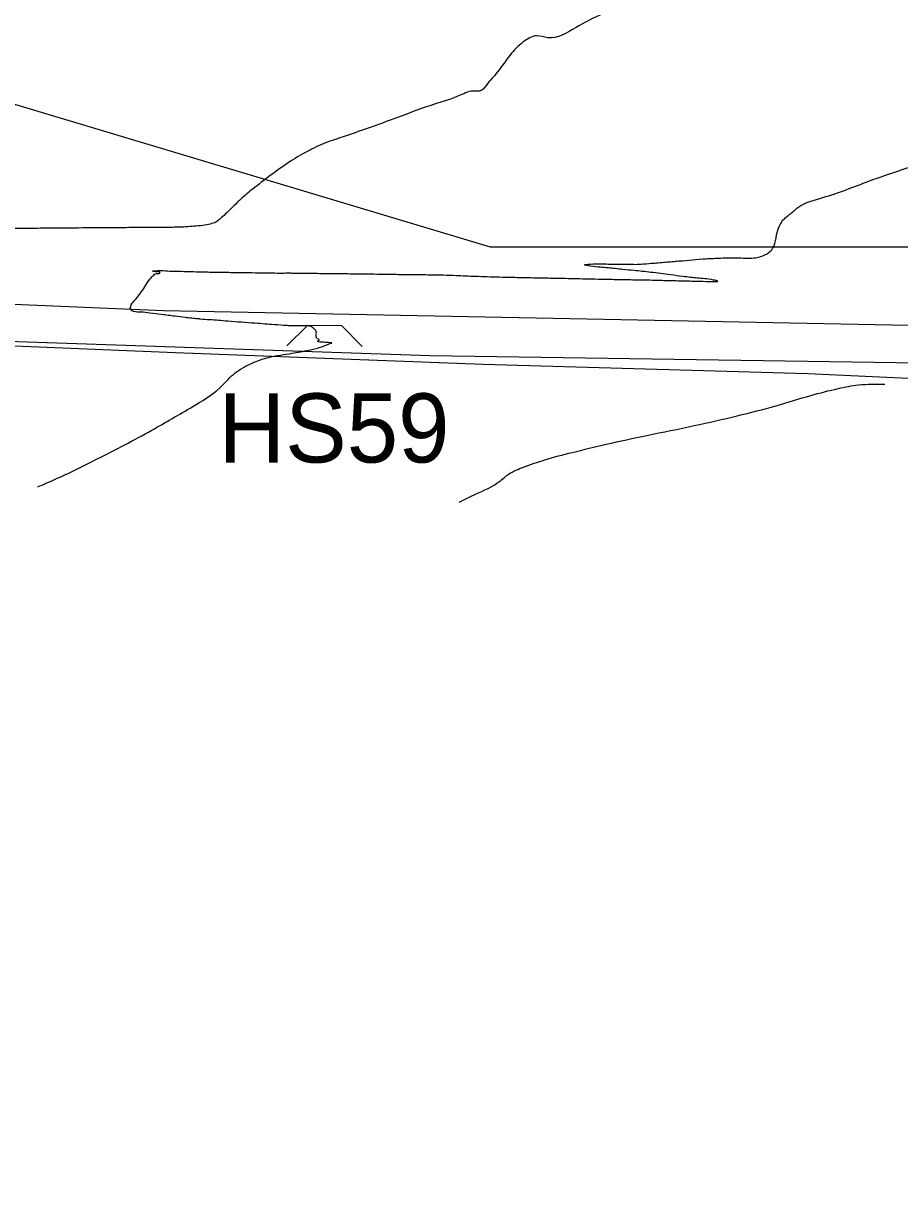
# Model space of a CAD drawing. Extents: x -478232 to -472707, y -1118753 to -1113967.
# Drawn here: x -477352.7 to -477225.9, y -1117543.2 to -1117372.8 of the extents above; entities that cross this region are included whole.
import ezdxf

# ---------------------------------------------------------------- set-up
doc = ezdxf.new("R2010")
doc.units = 0
for name, color, linetype in [('DESQ_pomoc', 7, 'Continuous'), ('hospodářské sjezdy', 7, 'Continuous'), ('ObPÚ', 7, 'Continuous'), ('silnice', 7, 'Continuous'), ('Vrstevnice_hlavni', 7, 'Continuous'), ('Vrstevnice_vedlejsi', 7, 'Continuous')]:
    doc.layers.add(name, color=color, linetype=linetype)

msp = doc.modelspace()

# ---------------------------------------------------------------- linework, layer by layer
at = {"layer": 'DESQ_pomoc'}
for points in [[(-477004.483, -1117160.333), (-477044.314, -1117201.613), (-476989.999, -1117272.585), (-476948.719, -1117345.73), (-476963.565, -1117360.938), (-477094.646, -1117397.148), (-477179.378, -1117405.115), (-477285.113, -1117405.115), (-477363.689, -1117381.578), (-477420.306, -1117340.062)], [(-477020.868, -1117742.21), (-477020.868, -1117712.88), (-477044.921, -1117619.616), (-477020.387, -1117525.382), (-477007.841, -1117474.78), (-476980.24, -1117427.384), (-476963.584, -1117391.711), (-476964.987, -1117380.26), (-476992.688, -1117391.394), (-477072.131, -1117410.121), (-477126.017, -1117419.251), (-477181.42, -1117422.538), (-477293.867, -1117420.815), (-477420.422, -1117416.561)]]:
    msp.add_lwpolyline(points, dxfattribs=at)
at = {"layer": 'hospodářské sjezdy'}
for p, q in [((-477314.616, -1117419.39), (-477311.569, -1117416.405)), ((-477311.569, -1117416.405), (-477306.684, -1117416.452)), ((-477306.684, -1117416.452), (-477303.695, -1117419.496))]:
    msp.add_line(p, q, dxfattribs=at)
at = {"layer": 'ObPÚ'}
msp.add_lwpolyline([(-476315.84, -1117537.76), (-476383.34, -1117541.03), (-476418.4, -1117542.71), (-476545.68, -1117541.31), (-476626.45, -1117531.73), (-476742.52, -1117514.65), (-476868.42, -1117495.62), (-476991.41, -1117464.75), (-477034.12, -1117456), (-477098.26, -1117446.89), (-477099.13, -1117418.94), (-477133.34, -1117422.81), (-477164.02, -1117425.11), (-477192.43, -1117425.62), (-477239.17, -1117423.45), (-477286.2, -1117422.09), (-477330.75, -1117420.42), (-477373.93, -1117418.61), (-477420.9, -1117417.49), (-477422.1, -1117417.56), (-477424.2, -1117417.6), (-477428.82, -1117417.33), (-477494.83, -1117414.18)], dxfattribs=at)
at = {"layer": 'silnice'}
msp.add_lwpolyline([(-478068.596, -1117511.329), (-477917.95, -1117462.993), (-477779.219, -1117418.245), (-477732.944, -1117407.585), (-477720.808, -1117405.048), (-477704.588, -1117403.835), (-477689.402, -1117401.926), (-477652.852, -1117401.691), (-477590.784, -1117403.37), (-477332.447, -1117414.279), (-477204.956, -1117416.797), (-477142.049, -1117416.797), (-477096.756, -1117410.083), (-477036.34, -1117397.174), (-476978.492, -1117379.033), (-476883.712, -1117344.626), (-476756.221, -1117298.47), (-476633.763, -1117254.832), (-476588.47, -1117242.245), (-476550.726, -1117234.692), (-476503.755, -1117230.496), (-476424.073, -1117228.817), (-476282.324, -1117220.425)], dxfattribs=at)
at = {"layer": 'Vrstevnice_hlavni'}
msp.add_spline([(-477289.678, -1117442), (-477287.302, -1117440.862), (-477283.774, -1117438.986), (-477282.509, -1117437.973), (-477280.339, -1117436.941), (-477277.265, -1117435.89), (-477273.286, -1117434.82), (-477268.352, -1117433.639), (-477262.464, -1117432.347), (-477255.622, -1117430.943), (-477249.39, -1117429.513), (-477243.767, -1117428.058), (-477238.754, -1117426.577), (-477234.779, -1117425.573), (-477231.842, -1117425.045), (-477228.043, -1117424.944)], degree=3, dxfattribs=at)
at = {"layer": 'Vrstevnice_vedlejsi'}
for points in [[(-477242.816, -1117401.206), (-477242.33, -1117400.788), (-477241.801, -1117400.341), (-477241.229, -1117399.866), (-477240.615, -1117399.363), (-477236.987, -1117397.929), (-477230.346, -1117395.561), (-477220.692, -1117392.262), (-477213.029, -1117389.419), (-477207.358, -1117387.033), (-477203.679, -1117385.104), (-477198.765, -1117383.705), (-477192.616, -1117382.835), (-477185.231, -1117382.494), (-477180.359, -1117379.804), (-477178.001, -1117374.763), (-477178.155, -1117367.373), (-477179.951, -1117358.721), (-477183.387, -1117348.807), (-477188.465, -1117337.631), (-477192.245, -1117329.464), (-477194.727, -1117324.304), (-477195.91, -1117322.151), (-477197.022, -1117320.01), (-477198.062, -1117317.881), (-477199.031, -1117315.762), (-477201.828, -1117310.612), (-477206.453, -1117302.429), (-477212.906, -1117291.215), (-477218.991, -1117279.805), (-477224.706, -1117268.2), (-477230.053, -1117256.4), (-477233.791, -1117248.023), (-477235.922, -1117243.067), (-477236.445, -1117241.534), (-477237.131, -1117240.196), (-477237.979, -1117239.054), (-477238.989, -1117238.108), (-477240.099, -1117237.792), (-477241.308, -1117238.108), (-477242.616, -1117239.054), (-477247.496, -1117242.927), (-477255.949, -1117249.728), (-477267.975, -1117259.456), (-477276.908, -1117266.227), (-477282.75, -1117270.039), (-477285.501, -1117270.894), (-477290.862, -1117272.253), (-477298.834, -1117274.115), (-477309.417, -1117276.481), (-477320.28, -1117277.55), (-477331.422, -1117277.32), (-477342.843, -1117275.793), (-477351.095, -1117274.483), (-477356.177, -1117273.39), (-477358.088, -1117272.515), (-477363.807, -1117268.569), (-477373.333, -1117261.552), (-477386.667, -1117251.464), (-477395.708, -1117244.586), (-477400.459, -1117240.917), (-477400.917, -1117240.459), (-477405.515, -1117237.519), (-477414.252, -1117232.098), (-477427.127, -1117224.195), (-477436.796, -1117218.202), (-477443.259, -1117214.119), (-477446.516, -1117211.946), (-477449.727, -1117209.411), (-477452.893, -1117206.515), (-477456.014, -1117203.258), (-477459.048, -1117199.241), (-477461.994, -1117194.464), (-477464.853, -1117188.928), (-477466.734, -1117184.683), (-477467.638, -1117181.729), (-477467.564, -1117180.066), (-477467.628, -1117178.904), (-477467.829, -1117178.243), (-477468.169, -1117178.084), (-477468.447, -1117177.976), (-477468.662, -1117177.92), (-477468.815, -1117177.914), (-477468.774, -1117177.844), (-477468.538, -1117177.708), (-477468.108, -1117177.506), (-477467.675, -1117177.3), (-477467.24, -1117177.089), (-477466.803, -1117176.874), (-477466.105, -1117176.551), (-477465.147, -1117176.119), (-477463.929, -1117175.579), (-477461.972, -1117174.773), (-477459.277, -1117173.703), (-477455.843, -1117172.368), (-477453.286, -1117171.289), (-477451.604, -1117170.465)], [(-477252.72, -1117332.72), (-477249.442, -1117350.907), (-477251.399, -1117358.647), (-477256.954, -1117365.034), (-477266.106, -1117370.068), (-477272.734, -1117373.328), (-477276.839, -1117374.815), (-477278.419, -1117374.529), (-477280.163, -1117375.266), (-477282.069, -1117377.024), (-477284.137, -1117379.804), (-477285.708, -1117381.646), (-477286.782, -1117382.55), (-477287.358, -1117382.516), (-477289.514, -1117383.138), (-477293.25, -1117384.416), (-477298.565, -1117386.349), (-477302.966, -1117387.928), (-477306.451, -1117389.154), (-477309.021, -1117390.026), (-477311.669, -1117391.276), (-477314.394, -1117392.903), (-477317.197, -1117394.908), (-477319.486, -1117396.657), (-477321.26, -1117398.15), (-477322.52, -1117399.387), (-477323.516, -1117400.341), (-477324.249, -1117401.012), (-477324.718, -1117401.399), (-477325.454, -1117401.703), (-477326.457, -1117401.923), (-477327.727, -1117402.06), (-477328.933, -1117402.16), (-477330.077, -1117402.221), (-477331.158, -1117402.245), (-477332.75, -1117402.264), (-477334.854, -1117402.279), (-477337.471, -1117402.29), (-477340.599, -1117402.31), (-477344.24, -1117402.337), (-477348.392, -1117402.371), (-477351.464, -1117402.395), (-477353.456, -1117402.406), (-477354.368, -1117402.406), (-477355.068, -1117402.403), (-477355.558, -1117402.399), (-477355.837, -1117402.392), (-477356.81, -1117402.42), (-477358.476, -1117402.483), (-477360.836, -1117402.58), (-477361.948, -1117402.705), (-477361.81, -1117402.861), (-477360.423, -1117403.045), (-477359.31, -1117403.205), (-477358.471, -1117403.34), (-477357.906, -1117403.451), (-477357.287, -1117403.611), (-477356.616, -1117403.818), (-477355.892, -1117404.072), (-477355.822, -1117404.241), (-477356.404, -1117404.324), (-477357.64, -1117404.32), (-477359.149, -1117404.327), (-477360.932, -1117404.343), (-477362.988, -1117404.369), (-477364.621, -1117404.377), (-477365.832, -1117404.368), (-477366.619, -1117404.34), (-477368.472, -1117404.314), (-477371.39, -1117404.29), (-477375.373, -1117404.266), (-477378.256, -1117404.244), (-477380.04, -1117404.225), (-477380.724, -1117404.208), (-477382.599, -1117404.115), (-477385.666, -1117403.945), (-477389.925, -1117403.698), (-477392.944, -1117403.533), (-477394.725, -1117403.45), (-477395.267, -1117403.448), (-477395.831, -1117403.442), (-477396.419, -1117403.433), (-477397.029, -1117403.42), (-477399.108, -1117403.384), (-477402.657, -1117403.323), (-477407.675, -1117403.239), (-477411.11, -1117403.18), (-477412.96, -1117403.147), (-477413.228, -1117403.138), (-477413.484, -1117403.113), (-477413.73, -1117403.071), (-477413.965, -1117403.013), (-477414.17, -1117402.951), (-477414.344, -1117402.886), (-477414.489, -1117402.817), (-477414.611, -1117402.734), (-477414.713, -1117402.635)], [(-477327.901, -1117415.45), (-477328.37, -1117415.407), (-477329.337, -1117415.294), (-477330.802, -1117415.109), (-477332.763, -1117414.853), (-477334.415, -1117414.652), (-477335.757, -1117414.508), (-477336.789, -1117414.419), (-477337.25, -1117414.076), (-477337.139, -1117413.48), (-477336.456, -1117412.63), (-477335.796, -1117411.752), (-477335.159, -1117410.844), (-477334.546, -1117409.906), (-477333.982, -1117409.264), (-477333.469, -1117408.918), (-477333.006, -1117408.867), (-477332.952, -1117408.792), (-477333.306, -1117408.693), (-477334.069, -1117408.572), (-477333.693, -1117408.518), (-477332.176, -1117408.533), (-477329.52, -1117408.616), (-477327.678, -1117408.673), (-477326.65, -1117408.701), (-477326.435, -1117408.702), (-477325.121, -1117408.721), (-477322.709, -1117408.756), (-477319.198, -1117408.809), (-477316.698, -1117408.842), (-477315.21, -1117408.856), (-477314.734, -1117408.85), (-477314.188, -1117408.85), (-477313.571, -1117408.855), (-477312.885, -1117408.866), (-477311.356, -1117408.884), (-477308.985, -1117408.911), (-477305.772, -1117408.946), (-477303.301, -1117408.975), (-477301.572, -1117408.998), (-477300.585, -1117409.016), (-477299.025, -1117409.038), (-477296.891, -1117409.065), (-477294.184, -1117409.097), (-477291.924, -1117409.139), (-477290.111, -1117409.192), (-477288.744, -1117409.255), (-477287.246, -1117409.315), (-477285.617, -1117409.37), (-477283.855, -1117409.421), (-477281.83, -1117409.471), (-477279.54, -1117409.519), (-477276.987, -1117409.566), (-477274.786, -1117409.61), (-477272.936, -1117409.65), (-477271.438, -1117409.687), (-477269.537, -1117409.727), (-477267.234, -1117409.771), (-477264.529, -1117409.817), (-477262.433, -1117409.857), (-477260.946, -1117409.889), (-477260.07, -1117409.915), (-477258.516, -1117409.953), (-477256.285, -1117410.005), (-477253.377, -1117410.07), (-477252.223, -1117410.023), (-477252.824, -1117409.865), (-477255.18, -1117409.597), (-477257.247, -1117409.351), (-477259.025, -1117409.129), (-477260.513, -1117408.931), (-477261.893, -1117408.76), (-477263.165, -1117408.617), (-477264.329, -1117408.502), (-477265.966, -1117408.334), (-477268.076, -1117408.115), (-477270.659, -1117407.844), (-477271.519, -1117407.66), (-477270.654, -1117407.563), (-477268.065, -1117407.553), (-477266.158, -1117407.555), (-477264.933, -1117407.569), (-477264.39, -1117407.597), (-477263.358, -1117407.557), (-477261.836, -1117407.45), (-477259.824, -1117407.277), (-477257.833, -1117407.109), (-477255.862, -1117406.946), (-477253.912, -1117406.788), (-477251.781, -1117406.689), (-477249.468, -1117406.647), (-477246.974, -1117406.663), (-477245.181, -1117406.113), (-477244.087, -1117404.995), (-477243.695, -1117403.31), (-477243.271, -1117402.047), (-477242.816, -1117401.206)], [(-477350.646, -1117439.791), (-477348.222, -1117438.741), (-477342.041, -1117435.763), (-477334.145, -1117431.602), (-477328.229, -1117428.175), (-477324.292, -1117425.483), (-477322.335, -1117423.525), (-477319.944, -1117422.038), (-477317.119, -1117421.021), (-477313.86, -1117420.475), (-477311.406, -1117420.004), (-477309.756, -1117419.607), (-477308.91, -1117419.286), (-477308.356, -1117419.07), (-477308.093, -1117418.96), (-477308.122, -1117418.955), (-477308.383, -1117418.936), (-477308.877, -1117418.903), (-477309.603, -1117418.855), (-477310.03, -1117418.794), (-477310.157, -1117418.722), (-477309.984, -1117418.638), (-477309.934, -1117418.546), (-477310.008, -1117418.448), (-477310.205, -1117418.342), (-477310.325, -1117418.174), (-477310.37, -1117417.944), (-477310.338, -1117417.652), (-477310.335, -1117417.428), (-477310.361, -1117417.271), (-477310.416, -1117417.183), (-477310.5, -1117417.084), (-477310.612, -1117416.976), (-477310.753, -1117416.857), (-477310.885, -1117416.749), (-477311.008, -1117416.654), (-477311.121, -1117416.57), (-477311.439, -1117416.518), (-477311.961, -1117416.496), (-477312.686, -1117416.504), (-477313.378, -1117416.501), (-477314.036, -1117416.486), (-477314.661, -1117416.458), (-477316.388, -1117416.339), (-477319.219, -1117416.129), (-477323.154, -1117415.827), (-477325.791, -1117415.625), (-477327.131, -1117415.52), (-477327.173, -1117415.514), (-477327.226, -1117415.508), (-477327.287, -1117415.503), (-477327.359, -1117415.498), (-477327.563, -1117415.48), (-477327.901, -1117415.45)]]:
    msp.add_spline(points, degree=3, dxfattribs=at)

# ---------------------------------------------------------------- texts
at = {"layer": 'hospodářské sjezdy'}
msp.add_text('HS59', height=10, rotation=359.99999, dxfattribs=at).set_placement((-477324.505, -1117436.277))

doc.saveas('drawing.dxf')
